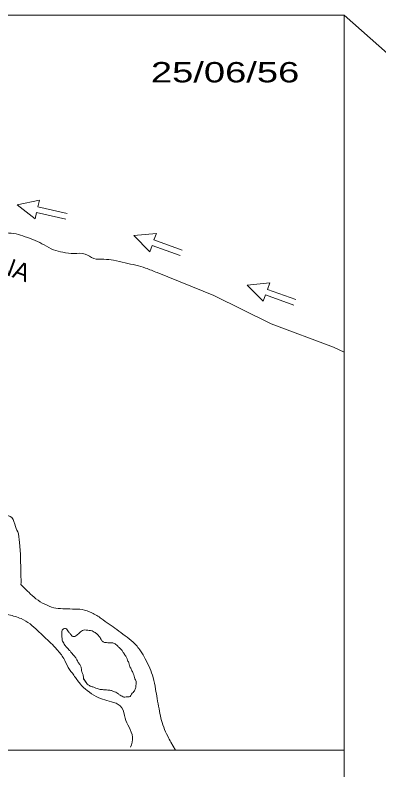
# Model space of a CAD drawing. Extents: x 3 to 328, y -131 to 329.
# Drawn here: x 124 to 165.1, y 154.8 to 240.2 of the extents above; entities that cross this region are included whole.
import ezdxf
from ezdxf.enums import TextEntityAlignment as Align

# ---------------------------------------------------------------- set-up
doc = ezdxf.new("R2010")
doc.units = 0
doc.header["$LTSCALE"] = 0.88
doc.layers.add('1', color=7, linetype='Continuous', lineweight=13)

msp = doc.modelspace()

# ---------------------------------------------------------------- linework, layer by layer
at = {"layer": '1'}
for p, q in [((161.12, 240.18), (307.23, 110.69)), ((131.68, 165.16), (132.06, 164.58)), ((131.68, 165.16), (132.06, 164.58)), ((132.06, 164.58), (131.68, 165.12)), ((161.12, 157.02), (35.23, 157.02)), ((122.66, 157.02), (136.89, 157.02)), ((138.97, 157.02), (138.17, 157.02))]:
    msp.add_line(p, q, dxfattribs=at)
msp.add_lwpolyline([(35.23, 240.18), (161.12, 240.18), (161.12, -20.55), (35.23, -20.55)], close=True, dxfattribs=at)
msp.add_lwpolyline([(35.23, 240.18), (161.12, 240.18), (161.12, -20.55), (35.23, -20.55)], close=True, dxfattribs=at)
for points in [[(129.84, 217.74), (126.53, 218.5), (126.7, 219.25), (124.19, 218.71)], [(129.69, 217.1), (126.38, 217.86), (126.21, 217.12), (124.19, 218.71)], [(142.84, 213.59), (139.65, 214.75), (139.92, 215.47), (137.36, 215.24)], [(142.62, 212.97), (139.43, 214.13), (139.17, 213.41), (137.36, 215.24)], [(161.12, 202.07), (159.94, 202.61), (152.89, 205.25), (146.42, 208.48), (140.01, 211.05)], [(140.01, 211.05), (146.42, 208.48), (152.89, 205.25), (159.94, 202.61), (161.12, 202.07)], [(155.67, 208), (152.48, 209.16), (152.75, 209.88), (150.19, 209.65)], [(155.45, 207.38), (152.26, 208.54), (152, 207.82), (150.19, 209.65)], [(141.56, 157.94), (142.08, 157.02), (161.12, 157.02), (161.12, 202.07)], [(124.36, 181.52), (124.44, 180.53), (124.58, 179.22), (124.6, 176.98), (124.63, 175.99), (124.62, 175.77)]]:
    msp.add_lwpolyline(points, dxfattribs=at)
for points in [[(140.01, 211.05), (138.71, 211.56), (137.61, 211.89), (136.4, 212.15), (135.09, 212.46), (134, 212.56), (132.85, 212.65), (131.89, 213.14), (130.59, 213.22), (129.37, 213.35), (128.31, 213.64), (127.25, 214.18), (126.23, 214.7), (125.1, 215.11), (124.07, 215.43), (122.97, 215.54), (121.77, 215.62), (120.62, 215.83), (119.43, 216.47), (118.34, 216.86), (117.16, 217.22), (116.13, 217.51), (114.95, 217.74), (113.72, 217.97), (112.52, 218.13), (111.48, 218.11), (110.45, 218.48), (109.51, 218.97), (108.43, 219.31), (107.23, 219.54), (106.21, 219.63), (105.12, 219.54), (104.07, 219.07), (105.29, 218.43), (106.41, 218.45), (106.96, 217.53), (106.98, 216.46), (108.12, 216.41), (109.08, 216.01), (109.59, 215.02), (110.88, 213.75)], [(140.01, 211.05), (138.71, 211.56), (137.61, 211.89), (136.4, 212.15), (135.09, 212.46), (134, 212.56), (132.85, 212.65), (131.89, 213.14), (130.59, 213.22), (129.37, 213.35), (128.31, 213.64), (127.25, 214.18), (126.23, 214.7), (125.1, 215.11), (124.07, 215.43), (122.97, 215.54), (121.77, 215.62), (120.62, 215.83), (119.43, 216.47), (118.34, 216.86), (117.16, 217.22), (116.13, 217.51), (114.95, 217.74), (113.72, 217.97), (112.52, 218.13), (111.48, 218.11), (110.45, 218.48), (109.51, 218.97), (108.43, 219.31), (107.23, 219.54), (106.21, 219.63), (105.12, 219.54), (104.07, 219.07), (105.29, 218.43), (106.41, 218.45), (106.96, 217.53), (106.98, 216.46), (108.12, 216.41), (109.08, 216.01), (109.59, 215.02), (110.88, 213.75)], [(114.98, 195.27), (115.64, 194.08), (116, 192.8), (116.2, 191.71), (116.3, 190.68), (116.47, 189.62), (116.77, 188.56), (117.44, 187.7), (118.4, 187.15), (119.17, 186.47), (119.96, 185.79), (121, 185.25), (121.74, 184.49), (122.61, 183.76), (123.59, 183.34), (123.99, 182.34), (124.36, 181.52)], [(114.98, 195.27), (115.64, 194.08), (116, 192.8), (116.2, 191.71), (116.3, 190.68), (116.47, 189.62), (116.77, 188.56), (117.44, 187.7), (118.4, 187.15), (119.17, 186.47), (119.96, 185.79), (121, 185.25), (121.74, 184.49), (122.61, 183.76), (123.59, 183.34), (123.99, 182.34), (124.36, 181.52)], [(137.01, 157.36), (137.22, 158.51), (136.84, 159.64), (136.39, 160.66), (136.03, 161.84), (135.09, 162.44), (134.09, 162.71), (133.11, 163.1), (132.12, 163.77), (131.32, 164.53), (130.6, 165.51), (129.97, 166.4), (129.45, 167.42), (128.69, 168.41), (128, 169.15), (127.24, 169.85), (126.49, 170.58), (125.65, 171.31), (124.63, 171.91), (123.27, 172.34), (122.06, 172.67), (121.1, 173.09), (120.16, 173.69), (119.37, 174.39), (118.45, 175.09), (117.32, 175.53), (116.42, 176.23), (115.6, 177.12), (114.83, 177.92), (114.13, 178.73), (113.22, 179.26), (112.68, 178.22), (112.61, 176.87), (112.66, 175.73), (112.76, 174.59), (113, 173.59), (113.5, 172.59), (114.2, 171.63), (114.93, 170.74), (115.86, 169.76), (116.71, 168.88), (117.53, 168.1), (118.36, 167.07), (119.14, 166.06), (119.81, 165.25), (120.77, 164.09), (121.49, 163.23), (122.22, 162.27), (122.62, 161.17), (122.72, 160.08), (122.61, 159.01), (122.58, 157.92), (122.54, 157.48)], [(124.62, 175.77), (125.5, 174.89), (126.32, 174.16), (127.33, 173.54), (128.32, 173.14), (129.36, 173.03), (130.43, 173), (131.53, 172.94), (132.63, 172.58), (133.7, 171.93), (134.6, 171.28), (135.46, 170.68), (136.38, 169.98), (137.3, 169.25), (138.13, 168.27), (138.67, 167.35), (139.18, 166.31), (139.55, 165.25), (139.83, 163.94), (140.01, 162.88), (140.23, 161.7), (140.43, 160.67), (140.75, 159.64), (141.2, 158.62), (141.56, 157.94)], [(124.62, 175.77), (125.5, 174.89), (126.32, 174.16), (127.33, 173.54), (128.32, 173.14), (129.36, 173.03), (130.43, 173), (131.53, 172.94), (132.63, 172.58), (133.7, 171.93), (134.6, 171.28), (135.46, 170.68), (136.38, 169.98), (137.3, 169.25), (138.13, 168.27), (138.67, 167.35), (139.18, 166.31), (139.55, 165.25), (139.83, 163.94), (140.01, 162.88), (140.23, 161.7), (140.43, 160.67), (140.75, 159.64), (141.2, 158.62), (141.56, 157.94)], [(131.68, 165.12), (131.64, 165.55), (131.49, 165.9), (131.45, 166.23), (131.34, 166.58), (131.17, 166.86), (131.04, 167.05), (130.95, 167.25), (130.76, 167.55), (130.5, 167.85), (130.31, 168.07), (130.12, 168.31), (129.94, 168.48), (129.8, 168.66), (129.59, 168.9), (129.45, 169.13), (129.32, 169.35), (129.28, 169.58), (129.24, 169.83), (129.23, 170.06), (129.25, 170.31), (129.29, 170.59), (129.43, 170.75), (129.64, 170.81), (129.85, 170.64), (130.01, 170.42), (130.22, 170.15), (130.49, 169.9), (130.72, 169.89), (130.94, 170.05), (131.11, 170.21), (131.45, 170.5), (131.68, 170.61), (131.98, 170.62), (132.34, 170.58), (132.65, 170.52), (132.91, 170.38), (133.24, 170.16), (133.49, 169.87), (133.62, 169.67), (133.76, 169.42), (134.07, 169.23), (134.28, 169.21), (134.61, 169.17), (134.89, 169.18), (135.25, 169.05), (135.46, 168.9), (135.72, 168.63), (135.91, 168.46), (136.04, 168.29), (136.23, 168.02), (136.34, 167.82), (136.48, 167.65), (136.61, 167.37), (136.7, 167.1), (136.81, 166.92), (136.88, 166.6), (137.02, 166.3), (137.21, 165.92), (137.3, 165.7), (137.41, 165.4), (137.5, 165.1), (137.61, 164.9), (137.62, 164.52), (137.59, 164.14), (137.45, 163.75), (137.31, 163.57), (137.11, 163.36), (136.95, 163.12), (136.72, 163.06), (136.49, 163.05), (136.26, 163.04), (136.06, 163.14), (135.82, 163.25), (135.56, 163.45), (135.33, 163.59), (135.07, 163.68), (134.76, 163.8), (134.55, 163.81), (134.3, 163.86), (134.07, 163.85), (133.84, 163.89), (133.58, 163.9), (133.33, 163.97), (133.1, 164.06), (132.76, 164.18), (132.56, 164.22), (132.35, 164.36), (132.11, 164.51), (132.06, 164.58)], [(131.68, 165.12), (131.64, 165.55), (131.49, 165.9), (131.45, 166.23), (131.34, 166.58), (131.17, 166.86), (131.04, 167.05), (130.95, 167.25), (130.76, 167.55), (130.5, 167.85), (130.31, 168.07), (130.12, 168.31), (129.94, 168.48), (129.8, 168.66), (129.59, 168.9), (129.45, 169.13), (129.32, 169.35), (129.28, 169.58), (129.24, 169.83), (129.23, 170.06), (129.25, 170.31), (129.29, 170.59), (129.43, 170.75), (129.64, 170.81), (129.85, 170.64), (130.01, 170.42), (130.22, 170.15), (130.49, 169.9), (130.72, 169.89), (130.94, 170.05), (131.11, 170.21), (131.45, 170.5), (131.68, 170.61), (131.98, 170.62), (132.34, 170.58), (132.65, 170.52), (132.91, 170.38), (133.24, 170.16), (133.49, 169.87), (133.62, 169.67), (133.76, 169.42), (134.07, 169.23), (134.28, 169.21), (134.61, 169.17), (134.89, 169.18), (135.25, 169.05), (135.46, 168.9), (135.72, 168.63), (135.91, 168.46), (136.04, 168.29), (136.23, 168.02), (136.34, 167.82), (136.48, 167.65), (136.61, 167.37), (136.7, 167.1), (136.81, 166.92), (136.88, 166.6), (137.02, 166.3), (137.21, 165.92), (137.3, 165.7), (137.41, 165.4), (137.5, 165.1), (137.61, 164.9), (137.62, 164.52), (137.59, 164.14), (137.45, 163.75), (137.31, 163.57), (137.11, 163.36), (136.95, 163.12), (136.72, 163.06), (136.49, 163.05), (136.26, 163.04), (136.06, 163.14), (135.82, 163.25), (135.56, 163.45), (135.33, 163.59), (135.07, 163.68), (134.76, 163.8), (134.55, 163.81), (134.3, 163.86), (134.07, 163.85), (133.84, 163.89), (133.58, 163.9), (133.33, 163.97), (133.1, 164.06), (132.76, 164.18), (132.56, 164.22), (132.35, 164.36), (132.11, 164.51), (132.06, 164.58)]]:
    msp.add_spline(points, degree=3, dxfattribs=at)

# ---------------------------------------------------------------- texts
at = {"layer": '1', "width": 1.4}
msp.add_text('25/06/56', height=2.3, dxfattribs=at).set_placement((147.685, 232.57), align=Align.CENTER)
at = {"layer": '1'}
msp.add_text('ATAFONA', height=2, rotation=340, dxfattribs=at).set_placement((119.273, 212.114), align=Align.CENTER)

doc.saveas('drawing.dxf')
